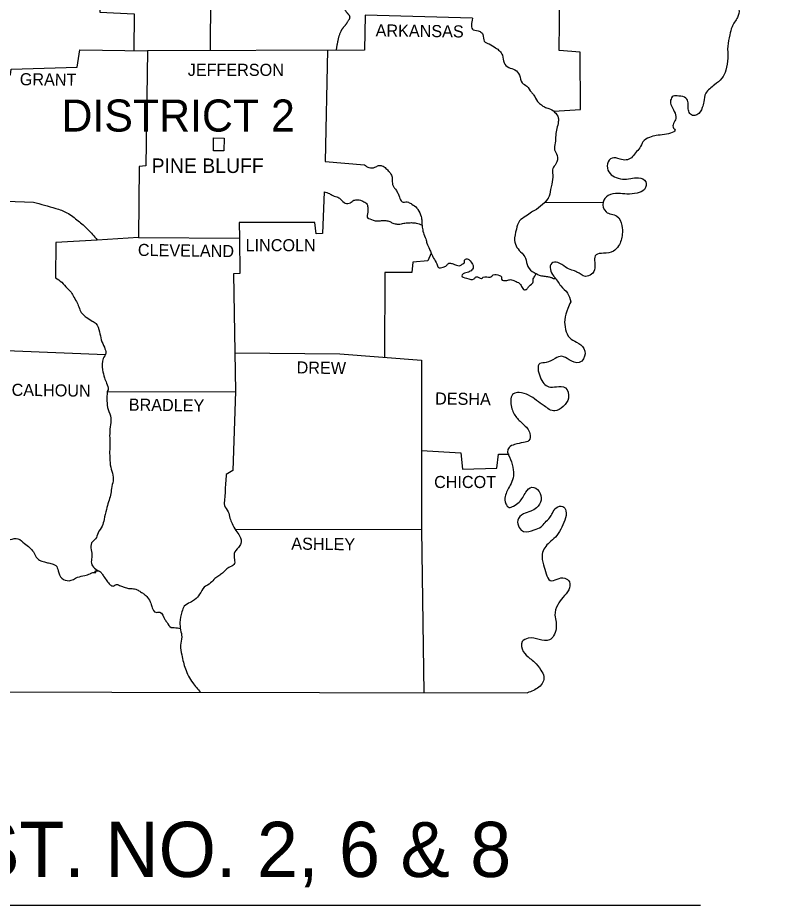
# Model space of a CAD drawing. Extents: x -819161 to 80911, y -6604 to 768454.
# Drawn here: x 62056 to 63538, y 6165 to 7879 of the extents above; entities that cross this region are included whole.
import ezdxf

# ---------------------------------------------------------------- set-up
doc = ezdxf.new("R2010")
doc.units = 0
doc.layers.add('Default', color=7, linetype='Continuous')

msp = doc.modelspace()

# ---------------------------------------------------------------- linework, layer by layer
at = {"layer": 'Default'}
for p, q in [((63073.2, 7521.7), (63186, 7522.3)), ((63073.2, 7521.7), (63186, 7522.3)), ((63092.6, 7374.8), (63094.3, 7374.8)), ((60968.3, 6164.9), (63373.8, 6164.9))]:
    msp.add_line(p, q, dxfattribs=at)
for points in [[(62363.4, 8252.4), (62395.2, 8250.6), (62395.8, 8041.1), (62367.2, 7922.5), (62428.2, 7919.4), (62427.2, 7815)], [(63090.8, 7697.9), (63142.1, 7701.3), (63141.8, 7812.1), (63101.3, 7815.2), (63103.5, 8032.4), (63069.3, 8037.4), (63068.3, 8183.6), (63537.6, 8186.8)], [(61936.8, 8116.1), (62002.1, 8112.1), (61999.6, 8043.6), (62071.2, 8040.8), (62072.8, 7981.1), (62106.4, 7978.3), (62106.4, 7968), (62138.4, 7965.5), (62139.4, 7927.2), (62211.6, 7927.2), (62214.1, 7889.2), (62280.7, 7886.1), (62280.3, 7814.9)], [(62933.6, 7877.7), (62726.3, 7883.6), (62725.1, 7816.1), (62306.2, 7814.6)], [(61990.9, 7742), (62021.4, 7746.7), (62023.6, 7765.4), (62041.6, 7768.5), (62042.9, 7779.4), (62170.5, 7783.4), (62175.5, 7816.4), (62306.2, 7814.6)], [(62306.2, 7814.6), (62303.4, 7592.3), (62290.3, 7591.4), (62289.1, 7454.2)], [(62653.6, 7815.8), (62649.4, 7600.8), (62725.1, 7594.8)], [(62647.6, 7542.2), (62644.5, 7462), (62631.7, 7461.6), (62629.2, 7483.4), (62483.6, 7483.1), (62483.8, 7453.2)], [(61980, 7526.5), (62086.1, 7522.6)], [(62209.4, 7449.4), (62129.1, 7444.5), (62128.5, 7376.1)], [(62289.1, 7454.2), (62209.4, 7449.4)], [(62289.1, 7454.2), (62483.8, 7453.2)], [(62483.8, 7453.2), (62484.5, 7384.5), (62472.7, 7384.1), (62476.1, 7157)], [(62854.2, 7424), (62847.4, 7409.4), (62818.4, 7406.6), (62816.9, 7386.6), (62764.6, 7386.6), (62764, 7223)], [(61826.8, 7243.6), (62049.7, 7235.4), (62225.3, 7228.5)], [(62475, 7231.3), (62677.4, 7229.5), (62835.2, 7217.7)], [(62835.2, 7217.7), (62835.5, 6889.9), (62839.9, 6575.3)], [(62228.4, 7156.3), (62476.1, 7157)], [(62476.1, 7157), (62470.8, 7004.5), (62458.4, 6996.7)], [(62835.4, 7043.2), (62911.5, 7038.4), (62914.6, 7007), (62980.9, 7008.8), (62984, 7035.9), (63004.4, 7035.9)], [(61031.4, 7021.6), (61032.7, 6578.4), (63039.7, 6575)], [(62475.9, 6890.6), (62835.5, 6890.9)]]:
    msp.add_lwpolyline(points, dxfattribs=at)
msp.add_lwpolyline([(62433.5, 7621.9), (62434.1, 7646.8), (62454.6, 7646.2), (62454, 7621.3)], close=True, dxfattribs=at)
for points in [[(63500.6, 8054.2), (63488.1, 8038.6), (63469.8, 8048.3), (63469.8, 8061.3), (63472.3, 8075.3), (63465.7, 8084.1), (63454.2, 8080.3), (63454.2, 8063.2), (63453, 8046.4), (63449.6, 8023.4), (63457.7, 8015.9), (63474.8, 8014), (63487.8, 8010.3), (63495.3, 7998.2), (63494.7, 7982.6), (63488.5, 7968), (63479.7, 7955.8), (63466.4, 7951.5), (63455.2, 7958.3), (63450.8, 7973), (63446.1, 7985.1), (63436.5, 7994.4), (63426.8, 7984.5), (63424.7, 7965.2), (63425.3, 7948.7), (63425, 7926), (63439.3, 7911.3), (63448.3, 7894.5), (63445.2, 7879.3), (63434.9, 7860.9), (63430.6, 7845.4), (63426.5, 7823.6), (63426.8, 7800.2), (63422.8, 7777.2), (63415.3, 7761.6), (63401, 7749.2), (63391.7, 7741.1), (63384.2, 7732.7), (63380.2, 7716.2), (63377.4, 7705), (63367.1, 7691), (63358.7, 7690.1), (63352.2, 7695.7), (63350.3, 7705), (63350, 7714), (63345.9, 7723.4), (63332.2, 7727.4), (63321.3, 7727.1), (63316.4, 7719.3), (63323.2, 7697.8), (63326.3, 7684.2), (63322, 7665.5), (63324.1, 7663.3), (63304.8, 7653), (63288.7, 7651.2), (63275.6, 7647.4), (63262.8, 7639), (63256.9, 7627.2), (63248.2, 7617.6), (63240.7, 7608.2), (63230.2, 7603.9), (63218.6, 7605.7), (63203.4, 7607.6), (63194.4, 7596.7), (63197.2, 7580.8), (63207.7, 7571.5), (63223.3, 7567.1), (63239.2, 7568.1), (63254.4, 7569.6), (63268.4, 7561.9), (63265.6, 7547.2), (63251.9, 7540.1), (63231.7, 7538.2), (63215.2, 7539.4), (63195.6, 7535.1), (63186, 7522.3), (63191.6, 7503.7), (63212.7, 7495.6), (63222.4, 7477.5), (63223, 7460.7), (63215.8, 7438), (63205.9, 7427.7), (63186.9, 7423.7), (63172.3, 7420.6), (63169.8, 7395.4), (63163.6, 7383.2), (63152, 7379.2), (63135.5, 7387.6), (63125.6, 7391.3), (63113.5, 7396.9), (63098.5, 7405.9), (63086.7, 7404.4), (63090.1, 7380.1), (63091, 7379.2), (63104.4, 7360.8), (63117.2, 7346.8), (63123.4, 7330)], [(62933.6, 7877.7), (62935.2, 7855.3), (62948.4, 7852), (62953.8, 7846), (62956.6, 7833.4), (62965.9, 7827.9), (62978.5, 7820.2), (62986.1, 7814.7), (62991.6, 7806), (62994.9, 7791.7), (63003.7, 7782.4), (63015.7, 7778.1), (63024.5, 7767.7), (63030, 7752.9), (63038.7, 7746.3), (63047.5, 7734.8), (63051.9, 7729.9), (63059.5, 7716.7), (63067.2, 7710.1), (63072.7, 7706.3), (63081.4, 7703.6), (63092.4, 7696.5), (63099.5, 7685.5), (63099.5, 7677.3), (63096.8, 7664.7), (63094.6, 7651.5), (63093.5, 7636.8), (63092.4, 7623.6), (63097.3, 7612.7), (63094.6, 7596.2), (63089.1, 7587.5), (63088.6, 7575.4), (63086.9, 7557.3), (63084.7, 7546.9), (63079.8, 7530), (63073.2, 7521.7)], [(62933.6, 7877.7), (62935.2, 7855.3), (62948.4, 7852), (62953.8, 7846), (62956.6, 7833.4), (62965.9, 7827.9), (62978.5, 7820.2), (62986.1, 7814.7), (62991.6, 7806), (62994.9, 7791.7), (63003.7, 7782.4), (63015.7, 7778.1), (63024.5, 7767.7), (63030, 7752.9), (63038.7, 7746.3), (63047.5, 7734.8), (63051.9, 7729.9), (63059.5, 7716.7), (63067.2, 7710.1), (63072.7, 7706.3), (63081.4, 7703.6), (63092.4, 7696.5), (63099.5, 7685.5), (63099.5, 7677.3), (63096.8, 7664.7), (63094.6, 7651.5), (63093.5, 7636.8), (63092.4, 7623.6), (63097.3, 7612.7), (63094.6, 7596.2), (63089.1, 7587.5), (63088.6, 7575.4), (63086.9, 7557.3), (63084.7, 7546.9), (63079.8, 7530), (63072.7, 7521.2)], [(62725.1, 7594.8), (62733.8, 7589.2), (62745.3, 7589.9), (62752.4, 7593), (62759, 7592.7), (62766.8, 7587.7), (62772.7, 7581.5), (62776.4, 7576.5), (62778.9, 7568.4), (62778.9, 7561.5), (62781.7, 7551.6), (62785.1, 7547.5), (62789.2, 7540.7), (62792.3, 7533.8), (62793.5, 7529.8), (62799.8, 7522.3), (62805.4, 7523.3), (62810, 7522.3), (62816.9, 7518.6), (62826.5, 7511.1), (62828.4, 7508.6), (62834.6, 7494.6), (62835.9, 7485.9), (62836.8, 7474.4), (62839, 7463.5), (62843.6, 7451.4), (62845.8, 7443.3), (62850.8, 7431.8), (62854.2, 7424), (62858.6, 7414.3), (62864.8, 7403.1), (62867.9, 7396.6), (62877.2, 7397.2), (62883.5, 7400), (62888.4, 7404.4), (62894.7, 7403.8), (62900.9, 7401.6), (62909.9, 7400), (62915.2, 7403.4), (62918.3, 7405.6), (62918.6, 7410.3), (62923.6, 7413.1), (62929.2, 7409), (62934.8, 7400.3), (62934.8, 7395), (62932.6, 7391.6), (62925.8, 7387.3), (62915.8, 7384.1), (62913, 7380.1), (62922.4, 7375.7), (62937, 7374.5), (62941, 7378.2), (62951, 7375.4), (62954.7, 7377.9), (62967.8, 7377.6), (62974, 7382), (62985.9, 7381), (62989.6, 7378.5), (62989.6, 7373.9), (62999.9, 7371.4), (63007, 7372.9), (63016, 7370.1), (63024.1, 7365.8), (63028.5, 7359.9), (63034.1, 7353.3), (63039.1, 7354.9), (63043.1, 7360.2), (63051.2, 7368.9), (63051.2, 7374.2), (63053.1, 7377.9), (63056.8, 7384.8)], [(62647.6, 7542.2), (62657.5, 7539.1), (62664.4, 7535.1), (62674, 7532), (62679.6, 7527.6), (62688.3, 7520.5), (62698, 7521.4), (62704.8, 7526.1), (62712, 7527), (62717.6, 7526.4), (62723.8, 7523.3), (62730.4, 7518), (62731.6, 7511.1), (62731.6, 7503), (62731.6, 7491.5), (62735.3, 7490), (62749, 7486.2), (62758.4, 7486.8), (62766.8, 7486.8), (62774.2, 7485.3), (62779.8, 7481.9), (62784.5, 7480.9), (62791, 7479.7), (62796.6, 7480.6), (62805.7, 7482.5), (62811.3, 7482.8), (62820.3, 7482.8), (62825.3, 7482.2), (62836.4, 7478.3)], [(62086.1, 7522.6), (62129.1, 7510.5), (62150.9, 7502.1), (62172.7, 7486.2), (62190.7, 7470.4), (62209.4, 7449.4)], [(63072.7, 7521.2), (63057.3, 7508.6), (63047.5, 7503.1), (63037.1, 7495.5), (63024.5, 7486.2), (63018.5, 7470.3), (63015.2, 7448.4), (63019.6, 7435.2), (63029.4, 7423.7), (63036, 7414.4), (63040.9, 7398), (63053, 7386.5), (63056.8, 7384.8)], [(62128.5, 7376.1), (62140.9, 7367.7), (62151.2, 7356.5), (62159, 7348.7), (62164.3, 7339), (62170.5, 7328.1), (62180.1, 7307.3), (62188.2, 7300.1), (62199.7, 7293), (62206.6, 7288.3), (62213.7, 7272.4), (62217.2, 7256.6), (62223.1, 7242.2), (62225.9, 7231.3), (62220.9, 7220.5), (62219.7, 7198.7), (62223.4, 7183.4), (62227.4, 7172.8), (62230.2, 7160.1), (62228.4, 7156.3)], [(63056.8, 7384.8), (63062.4, 7381.7), (63071.7, 7379.8), (63080.5, 7378.5), (63086.7, 7376.7), (63089.5, 7375.4), (63092.6, 7374.8)], [(63123.4, 7330), (63117.8, 7317.2), (63111.9, 7295.5), (63113.5, 7276.8), (63121.5, 7260.6), (63134.9, 7252.2), (63148.9, 7239.7), (63148.3, 7220.1), (63139.9, 7213), (63120.6, 7218), (63106, 7224.8), (63093.2, 7220.8), (63076.1, 7212.7), (63064, 7210.8), (63064.3, 7185), (63081.1, 7166), (63096, 7166), (63113.1, 7164.1), (63119.1, 7144.2), (63109.1, 7128), (63092.6, 7119.3), (63072.1, 7129.3), (63057.4, 7139.8), (63042.2, 7149.8), (63023.8, 7154.8), (63013.2, 7152.6), (63008.6, 7129.6), (63017.3, 7108.7), (63031.6, 7094.1), (63044.7, 7075.7), (63042.5, 7062), (63032.5, 7058.3), (63015.1, 7054.6), (63004.5, 7048.7), (63002, 7044.6), (63007.3, 7025.9), (63012.3, 7005.4), (63012.3, 6990.2), (63006.4, 6975.8), (62997.1, 6954.1), (62998, 6940.1), (63004.5, 6933.2), (63012.9, 6935.7), (63023.8, 6943.2), (63030.7, 6952.2), (63036.9, 6962.8), (63048.4, 6972.1), (63062.4, 6964), (63066.1, 6947.2), (63057.7, 6932.3), (63046.2, 6925.7), (63032.2, 6920.4), (63021.3, 6908.3), (63024.1, 6894), (63032.5, 6886.5), (63052.8, 6889.9), (63066.5, 6895.9), (63073.9, 6903.9), (63083.3, 6913.3), (63088.2, 6922.3), (63095.4, 6932.3), (63108.2, 6935.1), (63114.1, 6926.7), (63111.9, 6908.3), (63104.1, 6890.9), (63093.8, 6875.6), (63082.3, 6865.4), (63068.3, 6843), (63071.1, 6822.1), (63076.1, 6805), (63083.9, 6791.9), (63097, 6794.7), (63111.9, 6796.6), (63120.9, 6789.4), (63119.7, 6774.2), (63108.5, 6759.2), (63098.5, 6745.2), (63092.9, 6725), (63095.1, 6711.3), (63095.1, 6698.9), (63090.4, 6685.2), (63082.6, 6677.4), (63062.7, 6678.3), (63041.6, 6680.5), (63029.7, 6674), (63031.9, 6655), (63044.7, 6641.6), (63053.4, 6634.4), (63065.8, 6618.9), (63071.4, 6606.4), (63069.6, 6595.5), (63062.1, 6586.2), (63039.7, 6575)], [(62228.4, 7156.3), (62230.5, 7122.1), (62235.5, 7105.6), (62234.3, 7088.5), (62233.3, 7071.4), (62233.7, 7056.1), (62233.3, 7041.2), (62233.7, 7025.9), (62234.6, 7015.1), (62238.6, 6999.2), (62239.9, 6984.2), (62236.8, 6969.9), (62235.2, 6956.9), (62230.9, 6943.8), (62227.1, 6929.2), (62222.5, 6909.9), (62218.7, 6897.1), (62210.9, 6884), (62206, 6872.2), (62198.5, 6864.4), (62197.6, 6851.4), (62199.1, 6838.9), (62197.9, 6828), (62201.9, 6817.7), (62211.6, 6810.6)], [(62458.4, 6996.7), (62457.1, 6979.9), (62456.2, 6964), (62455.2, 6948.8), (62455.2, 6936.9), (62462.1, 6924.8), (62465.5, 6912.4), (62469.6, 6902.1), (62477, 6888.7), (62484.2, 6878.1), (62486.7, 6863.2), (62482, 6855.7), (62473.9, 6843.9), (62473.3, 6823), (62463.3, 6816.8), (62450.9, 6805.9), (62444, 6800.9), (62436.3, 6796), (62428.2, 6787.2), (62415.7, 6778.8), (62407, 6765.5), (62397.4, 6754.6), (62389, 6749.6), (62377.4, 6742.4), (62372.8, 6731.5), (62369, 6711), (62370.3, 6696.4), (62372.5, 6683), (62370, 6666.8), (62372.5, 6648.4), (62375.6, 6634.1), (62379.6, 6621.7), (62385.5, 6607.4), (62393.6, 6594.6), (62408.7, 6576.1)], [(61912.5, 6870.3), (61921.5, 6876.6), (61929.6, 6879.7), (61938, 6877.8), (61946.4, 6877.2), (61954.2, 6878.1), (61964.1, 6876.3), (61972.2, 6871.6), (61981.6, 6867.5), (61990.9, 6867.5), (61999, 6867.5), (62006.5, 6862.6), (62019.2, 6863.2), (62030.4, 6867.5), (62041.3, 6871), (62056.3, 6872.5), (62069, 6863.5), (62078.7, 6855.7), (62086.1, 6847), (62091.7, 6837), (62098, 6831.4), (62107.6, 6827.7), (62115.4, 6825.8), (62124.4, 6823.3), (62129.4, 6820.9), (62133.8, 6810.9), (62140.9, 6796.3), (62154.9, 6791.6), (62171.4, 6798.1), (62185.4, 6801.9), (62195.4, 6805), (62201, 6807.2), (62206.6, 6808.1), (62205.3, 6809), (62211.6, 6810.6), (62217.8, 6806.2), (62221.5, 6800.3), (62228.1, 6791.3), (62234, 6783.8), (62239.9, 6781.3), (62246.4, 6784.4), (62254.2, 6781.6), (62261.4, 6779.2), (62269.8, 6776.7), (62276.6, 6776.4), (62286.3, 6774.2), (62293.1, 6770.1), (62299.6, 6766.1), (62306.5, 6759.2), (62313, 6748), (62315.2, 6739.3), (62322.7, 6730.6), (62330.1, 6730.6), (62340.1, 6716.6), (62344.1, 6711), (62352.2, 6701.4), (62358.1, 6701), (62369.9, 6699.2)]]:
    msp.add_spline(points, degree=3, dxfattribs=at)
msp.add_open_spline([(62658.8, 7967.7), (62659.9, 7966.9), (62661.1, 7966.2), (62662.2, 7965.4), (62663.4, 7964.6), (62664.5, 7963.9), (62665.7, 7963.1), (62667.9, 7961.5), (62670.2, 7959.9), (62672.5, 7958.3), (62673.7, 7957.5), (62674.9, 7956.7), (62676.1, 7955.9), (62677.3, 7955.1), (62678.5, 7954.3), (62679.6, 7953.5), (62680.9, 7952.6), (62682, 7951.7), (62683.1, 7950.8), (62683.7, 7950.3), (62684.3, 7949.7), (62684.8, 7949.2), (62685.1, 7948.9), (62685.4, 7948.6), (62685.6, 7948.3), (62685.9, 7948), (62686.2, 7947.7), (62686.5, 7947.4), (62687.4, 7946.4), (62688.1, 7945.3), (62688.7, 7944.1), (62689.2, 7942.9), (62689.6, 7941.7), (62689.9, 7940.4), (62690.1, 7939.1), (62690.3, 7937.9), (62690.4, 7936.6), (62690.4, 7936), (62690.4, 7935.3), (62690.5, 7934.7), (62690.5, 7934.1), (62690.5, 7933.4), (62690.5, 7932.8), (62690.5, 7932), (62690.5, 7931.1), (62690.5, 7930.2), (62690.5, 7929.4), (62690.4, 7928.5), (62690.3, 7927.7), (62690.2, 7926.8), (62690.1, 7925.9), (62689.9, 7925.1), (62689.7, 7924.2), (62689.5, 7923.4), (62689.3, 7922.5), (62689, 7921.8), (62688.7, 7921), (62688.3, 7920.3), (62687.9, 7919.6), (62687.5, 7918.9), (62687.1, 7918.1), (62686.7, 7917.4), (62686.3, 7916.7), (62685.9, 7916), (62685.5, 7915.3), (62685.2, 7914.6), (62684.9, 7913.8), (62684.7, 7913.3), (62684.5, 7912.7), (62684.3, 7912.1), (62684.1, 7911.6), (62684, 7911), (62683.8, 7910.4), (62683.4, 7909.2), (62683.1, 7908), (62682.9, 7906.7), (62682.7, 7905.6), (62682.7, 7904.3), (62682.7, 7903.1), (62682.8, 7902.6), (62682.9, 7902), (62683, 7901.4), (62683.2, 7900.9), (62683.4, 7900.3), (62683.7, 7899.8), (62684.6, 7898.1), (62685.7, 7896.4), (62686.8, 7894.7), (62687.9, 7893.1), (62689, 7891.5), (62690.2, 7889.9), (62690.7, 7889.2), (62691.2, 7888.6), (62691.7, 7887.9), (62692.3, 7887.3), (62692.8, 7886.6), (62693.4, 7886), (62694.1, 7885.1), (62694.9, 7884.1), (62695.6, 7883.1), (62695.7, 7882.9), (62695.8, 7882.8), (62695.9, 7882.6), (62695.9, 7882.4), (62696, 7882.3), (62696.1, 7882.1), (62696.6, 7881), (62696.8, 7879.7), (62696.5, 7878.5), (62696.3, 7877.2), (62695.8, 7875.9), (62695.1, 7874.7), (62693.9, 7872.8), (62692.6, 7870.8), (62691.4, 7868.9), (62691, 7868.3), (62690.6, 7867.7), (62690.2, 7867.1), (62689.8, 7866.5), (62689.4, 7865.9), (62689, 7865.3), (62688.5, 7864.7), (62688.1, 7864.1), (62687.6, 7863.6), (62686.7, 7862.5), (62685.8, 7861.4), (62684.8, 7860.2), (62683.9, 7859.1), (62683, 7858), (62682.2, 7856.8), (62681.7, 7856.3), (62681.3, 7855.7), (62681, 7855.1), (62680.6, 7854.4), (62680.3, 7853.8), (62679.9, 7853.1), (62678.8, 7850.8), (62677.7, 7848.3), (62676.8, 7845.8), (62676, 7843.3), (62675.2, 7840.8), (62674.6, 7838.2), (62674.2, 7836.4), (62673.8, 7834.5), (62673.5, 7832.6), (62673.1, 7830.8), (62672.7, 7828.9), (62672.3, 7827.1), (62671.9, 7825.2), (62671.6, 7823.4), (62671.3, 7821.5), (62671, 7819.6), (62670.7, 7817.8), (62670.4, 7815.9)], degree=3, dxfattribs=at)

# ---------------------------------------------------------------- texts
for s, rotation, p in [('ARKANSAS', 359.2655, (62746.7, 7842.6)), ('GRANT', 359.3139, (62059.7, 7748.3)), ('CLEVELAND', 359.2412, (62287.7, 7418.7)), ('DREW', 359.1352, (62594.1, 7191.8)), ('CALHOUN', 359.2686, (62043.9, 7148.6)), ('DESHA', 359.2949, (62861.5, 7131.8)), ('BRADLEY', 359.2655, (62270.1, 7120)), ('ASHLEY', 359.2711, (62583.9, 6851.7))]:
    msp.add_text(s, height=23.34, rotation=rotation, dxfattribs=at).set_placement(p)
for s, height, p in [('JEFFERSON', 23.34, (62384.1, 7766.3)), ('DISTRICT 2', 61.88, (62140.3, 7658.8)), ('PINE BLUFF', 28.01, (62314.3, 7578.8)), ('LINCOLN', 23.34, (62495.8, 7427.7)), ('CHICOT', 23.34, (62859.7, 6970.5)), ('ARK. HWY. DIST. NO. 2, 6 & 8', 106.498, (61038.1, 6219.5))]:
    msp.add_text(s, height=height, dxfattribs=at).set_placement(p)

doc.saveas('drawing.dxf')
